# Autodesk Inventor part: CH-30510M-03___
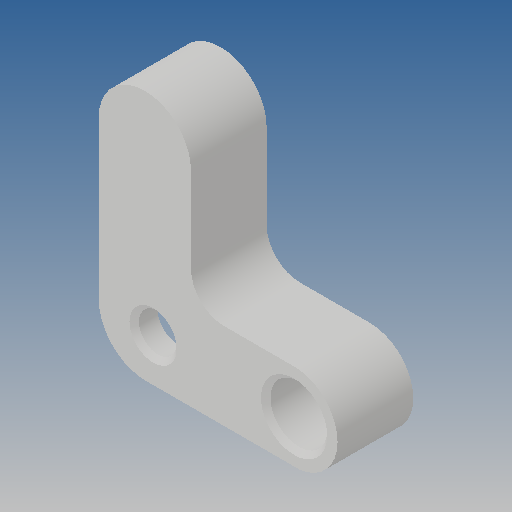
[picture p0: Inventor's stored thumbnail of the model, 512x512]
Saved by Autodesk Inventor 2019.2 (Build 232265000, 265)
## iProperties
Created: 2010-06
Part Number: CH-30510M-03___
Material: Ogólny
Document SubType Name: Modeling
Designer: CADENGINEERING4
Density: 1 g/cm^3
Appearance: Domyślna
Author: CADENGINEERING4
Revision Number: ANY
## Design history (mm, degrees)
feature "NONE"
node "Bryła1"
